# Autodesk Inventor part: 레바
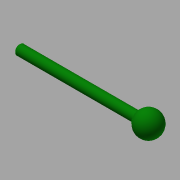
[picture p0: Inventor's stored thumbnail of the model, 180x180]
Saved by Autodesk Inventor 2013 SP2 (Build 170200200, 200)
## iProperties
Created: 2015-12
Part Number: 레바
Material: 스테인리스강
Document SubType Name: Modeling
Designer: mduedu
Density: 8.08 g/cm^3
Mass: 30.7693 g
Surface Area: 20.8622 cm^2
Volume: 3.80808 cm^3
Author: mduedu
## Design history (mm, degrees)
sketch "스케치1"
  geometry: C1 r 3 at (0, 0); 1 further point
  constraints: 1 centre point, 1 coincident
  dimensions: "d0" = 6 diameter of C1
extrude "돌출1" new body sketch "스케치1" distance "d1" = 80; taper "d2" = 0 deg
sketch "스케치2"
  geometry: L1 (7.5, 0)-(-6, 0); L2 (-6, 4.5)-(-6, 0); A1 r 7.5 centre (0, 0) between (7.5, 0) and (-6, 4.5); 2 further points
  constraints: 4 end point, 2 coincident, 2 point on circle, 1 centre point, 1 horizontal, 1 perpendicular, 1 point on line
  dimensions: "d3" = 15 diameter of A1; "d10" = 6 distance from line of L2 point (0, 0)
revolve "회전1" sketch "스케치2" stored, may be unused: angle "d4" = 90 deg
chamfer "모따기1" distance "d7" = 0.5; stored, may be unused: second distance "d8" = 2, angle "d9" = 45 deg
fillet "모깎기2" dims "d11" = 0.3
node "솔리드1"
